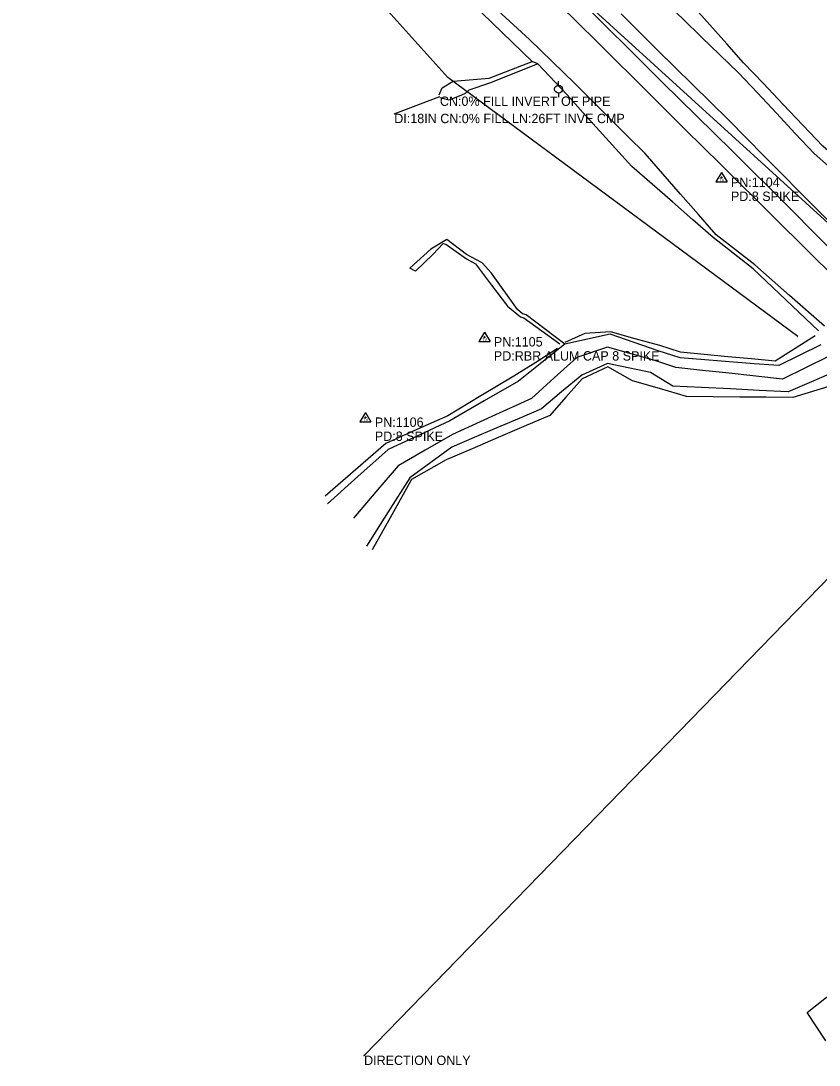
# Model space of a CAD drawing. Extents: x 1660112 to 1662239, y 668919 to 671377.
# Drawn here: x 1660814 to 1661240, y 669846 to 670403 of the extents above; entities that cross this region are included whole.
import ezdxf

# ---------------------------------------------------------------- set-up
doc = ezdxf.new("R2010")
doc.units = 0
for name, color, linetype in [('S_BASELINE', 7, 'Continuous'), ('S_DITCHLINE', 7, 'Continuous'), ('S_DRG_PT_SYM', 7, 'Continuous'), ('S_DRIVEWAY', 7, 'Continuous'), ('S_EDGE_PAVEMENT', 7, 'Continuous'), ('S_PAVEMENT_CROWN', 7, 'Continuous'), ('S_SANITARY_SEWER', 7, 'Continuous'), ('S_SANITARY_SEWER_ANNOT', 7, 'Continuous'), ('S_SECONDARY_CTL', 7, 'Continuous'), ('S_SECONDARY_CTL_ANNOT', 7, 'Continuous'), ('S_SIDE_DRAIN', 7, 'Continuous'), ('S_SIDE_DRAIN_ANNOT', 7, 'Continuous'), ('S_STREAM', 7, 'Continuous'), ('S_UTILITY_POLE', 7, 'Continuous'), ('S_UTL_PT_SYM', 7, 'Continuous'), ('S_WATER_UTILITIES', 7, 'Continuous')]:
    doc.layers.add(name, color=color, linetype=linetype)

msp = doc.modelspace()

# ---------------------------------------------------------------- linework, layer by layer
at = {"layer": 'S_BASELINE'}
msp.add_line((1660813.76, 670687.35), (1661335.19, 670212.07), dxfattribs=at)
at = {"layer": 'S_DITCHLINE'}
for points in [[(1661292.16, 670275.66), (1661274.83, 670292.21), (1661270.79, 670300.84), (1661264.75, 670307.54), (1661250.97, 670319.7), (1661237.18, 670331.85), (1661227.07, 670342.64), (1661216.95, 670353.42), (1661206.84, 670364.21), (1661196.72, 670375), (1661186.88, 670384.5), (1661177.03, 670394.01), (1661167.19, 670403.51), (1661157.34, 670413.01), (1661144.39, 670427.16), (1661131.45, 670441.31), (1661118.5, 670455.46), (1661105.55, 670469.61)], [(1661299.45, 670280.74), (1661284.47, 670292.7), (1661279.2, 670294.55), (1661276.17, 670300.4), (1661276.07, 670306.25), (1661258.9, 670321.05), (1661241.72, 670335.84), (1661231.17, 670346.95), (1661220.61, 670358.06), (1661210.06, 670369.17), (1661199.5, 670380.28), (1661190.45, 670390.39), (1661181.41, 670400.5), (1661172.36, 670410.61), (1661163.31, 670420.71), (1661149.32, 670433.4), (1661135.33, 670446.1), (1661121.34, 670458.79), (1661107.35, 670471.48)], [(1661239.43, 670237.24), (1661221.97, 670253.79), (1661204.51, 670270.33), (1661193.84, 670278.71), (1661183.17, 670287.08), (1661172.33, 670296.55), (1661161.49, 670306.02), (1661150.65, 670315.49), (1661139.81, 670324.96), (1661131.17, 670334.51), (1661122.52, 670344.05), (1661113.88, 670353.6), (1661105.24, 670363.14), (1661089.73, 670379.71), (1661086.66, 670381), (1661070.62, 670396.48), (1661054.58, 670411.96)], [(1661242.65, 670239.7), (1661224.03, 670256.09), (1661205.42, 670272.49), (1661195.13, 670280.52), (1661184.84, 670288.55), (1661175.36, 670299.38), (1661165.88, 670310.21), (1661156.4, 670321.03), (1661146.92, 670331.86), (1661137.55, 670341.19), (1661128.17, 670350.53), (1661118.79, 670359.86), (1661109.42, 670369.2), (1661097.31, 670380.98), (1661085.2, 670392.76), (1661068.34, 670408.15)], [(1661037.01, 670363.11), (1661038.52, 670366.98), (1661044.5, 670370.41), (1661063.67, 670371.99), (1661086.7, 670380.95)], [(1661089.74, 670379.7), (1661076.81, 670374.57), (1661063.88, 670369.43), (1661052.89, 670365.68), (1661050.81, 670363.81), (1661048.98, 670362.94), (1661042.37, 670360.33), (1661037.54, 670361.63)], [(1661104.14, 670230.16), (1661093.8, 670237.99), (1661083.46, 670245.82), (1661081.52, 670246.32), (1661078.79, 670248.62), (1661064.86, 670267.98), (1661059.89, 670273.58), (1661051.63, 670278.02), (1661041.16, 670286.08), (1661032.48, 670280.84), (1661021.33, 670270.78)], [(1661024.28, 670269.05), (1661033.67, 670278.04), (1661039.06, 670283.92), (1661040.59, 670283.48), (1661051.57, 670275.75), (1661056.38, 670272.93), (1661064.89, 670261.7), (1661073.41, 670250.48), (1661080.49, 670244.77), (1661082.16, 670244.13), (1661101.34, 670230.28)], [(1661024.28, 670269.05), (1661021.33, 670270.78)]]:
    msp.add_lwpolyline(points, dxfattribs=at)
at = {"layer": 'S_DRG_PT_SYM'}
for points in [[(1661037.39, 670362.29), (1661037.39, 670362.34), (1661037.39, 670362.29), (1661037.34, 670362.29), (1661037.39, 670362.29), (1661037.39, 670362.24), (1661037.39, 670362.29), (1661037.44, 670362.29)], [(1661013.05, 670353.07), (1661013.05, 670353.12), (1661013.05, 670353.07), (1661013, 670353.07), (1661013.05, 670353.07), (1661013.05, 670353.02), (1661013.05, 670353.07), (1661013.1, 670353.07)]]:
    msp.add_lwpolyline(points, dxfattribs=at)
at = {"layer": 'S_DRIVEWAY'}
msp.add_lwpolyline([(1661243.33, 669858.48), (1661233.44, 669873.57), (1661243.64, 669881.7), (1661257.23, 669871.4)], dxfattribs=at)
at = {"layer": 'S_EDGE_PAVEMENT'}
for points in [[(1661249.53, 670264.29), (1661232.81, 670280.83), (1661216.09, 670297.37), (1661206.48, 670306.91), (1661196.87, 670316.45), (1661187.26, 670325.99), (1661177.65, 670335.53), (1661168.35, 670344.75), (1661159.06, 670353.98), (1661149.76, 670363.2), (1661140.47, 670372.43), (1661130.68, 670382.11), (1661120.89, 670391.8), (1661111.1, 670401.49), (1661101.31, 670411.17)], [(1661262.8, 670277.66), (1661246.17, 670294.45), (1661229.53, 670311.23), (1661220, 670320.86), (1661210.47, 670330.49), (1661200.95, 670340.13), (1661191.42, 670349.76), (1661181.92, 670359.12), (1661172.42, 670368.49), (1661162.93, 670377.85), (1661153.43, 670387.22), (1661143.78, 670396.82), (1661134.14, 670406.42)]]:
    msp.add_lwpolyline(points, dxfattribs=at)
at = {"layer": 'S_PAVEMENT_CROWN'}
msp.add_lwpolyline([(1661256.17, 670270.41), (1661239.48, 670287.26), (1661222.79, 670304.1), (1661213.05, 670313.75), (1661203.32, 670323.4), (1661193.59, 670333.05), (1661183.85, 670342.7), (1661174.57, 670351.81), (1661165.29, 670360.92), (1661156.01, 670370.03), (1661146.73, 670379.14), (1661137.08, 670388.79), (1661127.43, 670398.43), (1661117.78, 670408.07)], dxfattribs=at)
at = {"layer": 'S_SANITARY_SEWER'}
msp.add_line((1661289.08, 670151.19), (1660996.93, 669850.58), dxfattribs=at)
at = {"layer": 'S_SECONDARY_CTL'}
for p, q in [((1661187.72, 670321.67), (1661184.71, 670316.72)), ((1661187.72, 670321.67), (1661190.67, 670316.72)), ((1661184.71, 670316.72), (1661190.67, 670316.72)), ((1661061.19, 670236.52), (1661058.18, 670231.56)), ((1661061.19, 670236.52), (1661064.14, 670231.56)), ((1661058.18, 670231.56), (1661064.14, 670231.56)), ((1660997.66, 670193.65), (1660994.65, 670188.69)), ((1660994.65, 670188.69), (1661000.61, 670188.69)), ((1660997.66, 670193.65), (1661000.61, 670188.69))]:
    msp.add_line(p, q, dxfattribs=at)
for centre, radius in [((1661187.72, 670319.06), 0.311), ((1661187.72, 670319.06), 0.183), ((1661187.72, 670319.06), 0.103), ((1661061.19, 670233.91), 0.311), ((1661061.19, 670233.91), 0.183), ((1661061.19, 670233.91), 0.103), ((1660997.66, 670191.04), 0.311), ((1660997.66, 670191.04), 0.183), ((1660997.66, 670191.04), 0.103)]:
    msp.add_circle(centre, radius, dxfattribs=at)
at = {"layer": 'S_SIDE_DRAIN'}
msp.add_line((1661013.05, 670353.07), (1661037.39, 670362.29), dxfattribs=at)
at = {"layer": 'S_STREAM'}
for points in [[(1661240.7, 670229.82), (1661218.36, 670218.7), (1661205.19, 670219.73), (1661192.01, 670220.76), (1661178.84, 670221.78), (1661165.66, 670222.81), (1661153.9, 670226.65), (1661141.09, 670231.09), (1661128.28, 670235.52), (1661104.13, 670230.16), (1661091.73, 670220.31), (1661079.33, 670210.47), (1661061.05, 670199.86), (1661042.76, 670189.25), (1661026.29, 670181.65), (1661009.82, 670174.04), (1660993.64, 670159.54), (1660977.45, 670145.03)], [(1661237.64, 670234.64), (1661226.98, 670227.9), (1661216.31, 670221.16), (1661203.67, 670222.32), (1661191.03, 670223.48), (1661178.4, 670224.64), (1661165.76, 670225.81), (1661154.74, 670229.38), (1661141.63, 670233.02), (1661128.51, 670236.67), (1661114.77, 670235.78), (1661104.13, 670231.11)], [(1661100.22, 670227.77), (1661088.57, 670220.41), (1661076.93, 670213.05), (1661059.25, 670202.53), (1661041.58, 670192), (1661025.06, 670184.59), (1661008.55, 670177.19), (1660992.32, 670163.1), (1660976.09, 670149)], [(1661244.82, 670223.57), (1661232.52, 670217.57), (1661220.23, 670211.57), (1661206.02, 670213.11), (1661191.8, 670214.64), (1661177.59, 670216.17), (1661163.37, 670217.71), (1661152.07, 670221.36), (1661139.48, 670224.92), (1661126.88, 670228.48), (1661110.47, 670223.04), (1661098.36, 670212.14), (1661086.24, 670201.24), (1661065.14, 670191.58), (1661044.04, 670181.92), (1661029.55, 670173.61), (1661015.06, 670165.29), (1661003.14, 670151.31), (1660991.22, 670137.34)], [(1661250.84, 670216.6), (1661237.04, 670210.68), (1661223.24, 670204.75), (1661207.85, 670205.5), (1661192.45, 670206.25), (1661177.06, 670207), (1661161.67, 670207.75), (1661149.8, 670215.11), (1661126.76, 670219.9), (1661113.07, 670213.68), (1661102.32, 670204.64), (1661091.57, 670195.6), (1661079.63, 670190.52), (1661067.69, 670185.43), (1661055.75, 670180.35), (1661043.81, 670175.26), (1661032.6, 670167.06), (1661021.38, 670158.86), (1661009.82, 670140.66), (1660998.25, 670122.45)], [(1661254.7, 670214.48), (1661247.25, 670208.21), (1661225.75, 670201.67), (1661211.58, 670201.81), (1661197.41, 670201.96), (1661183.24, 670202.1), (1661169.07, 670202.24), (1661154.61, 670206.46), (1661140.15, 670210.67), (1661126.98, 670218.08), (1661113.36, 670211.62), (1661104.67, 670201.88), (1661095.98, 670192.14), (1661082.19, 670186.21), (1661068.4, 670180.28), (1661054.61, 670174.34), (1661040.82, 670168.41), (1661022.25, 670157.95), (1661011.73, 670139.15), (1661001.22, 670120.35)]]:
    msp.add_lwpolyline(points, dxfattribs=at)
at = {"layer": 'S_UTILITY_POLE'}
for p, q in [((1661100.73, 670368.27), (1661100.73, 670370.4)), ((1661100.73, 670364.05), (1661100.73, 670361.99))]:
    msp.add_line(p, q, dxfattribs=at)
msp.add_circle((1661100.75, 670366.19), 2.11, dxfattribs=at)
at = {"layer": 'S_UTL_PT_SYM'}
for points in [[(1661041.63, 670372.43), (1661041.63, 670372.48), (1661041.63, 670372.43), (1661041.58, 670372.43), (1661041.63, 670372.43), (1661041.63, 670372.38), (1661041.63, 670372.43), (1661041.68, 670372.43)], [(1661228.37, 670234.25), (1661228.37, 670234.3), (1661228.37, 670234.25), (1661228.32, 670234.25), (1661228.37, 670234.25), (1661228.37, 670234.2), (1661228.37, 670234.25), (1661228.42, 670234.25)], [(1660996.93, 669850.58), (1660996.93, 669850.63), (1660996.93, 669850.58), (1660996.88, 669850.58), (1660996.93, 669850.58), (1660996.93, 669850.53), (1660996.93, 669850.58), (1660996.98, 669850.58)]]:
    msp.add_lwpolyline(points, dxfattribs=at)
at = {"layer": 'S_WATER_UTILITIES'}
for p, q in [((1661041.63, 670372.43), (1660939.86, 670485.61)), ((1661228.37, 670234.25), (1661041.63, 670372.43))]:
    msp.add_line(p, q, dxfattribs=at)

# ---------------------------------------------------------------- texts
at = {"layer": 'S_SANITARY_SEWER_ANNOT'}
msp.add_text('DIRECTION ONLY', height=5, dxfattribs=at).set_placement((1660996.93, 669845.58))
at = {"layer": 'S_SECONDARY_CTL'}
for p in [(1661186.52, 670317.05), (1661059.99, 670231.9), (1660996.46, 670189.03)]:
    msp.add_text('TV', height=1.5, rotation=360, dxfattribs=at).set_placement(p)
at = {"layer": 'S_SECONDARY_CTL_ANNOT'}
for s, p in [('PN:1104', (1661192.72, 670314.06)), ('PD:8 SPIKE', (1661192.72, 670306.56)), ('PN:1105', (1661066.19, 670228.91)), ('PD:RBR ALUM CAP 8 SPIKE', (1661066.19, 670221.41)), ('PN:1106', (1661002.66, 670186.04)), ('PD:8 SPIKE', (1661002.66, 670178.54))]:
    msp.add_text(s, height=5, dxfattribs=at).set_placement(p)
at = {"layer": 'S_SIDE_DRAIN_ANNOT'}
for s, p in [('CN:0% FILL INVERT OF PIPE', (1661037.39, 670357.29)), ('DI:18IN CN:0% FILL LN:26FT INVE CMP', (1661013.05, 670348.07))]:
    msp.add_text(s, height=5, dxfattribs=at).set_placement(p)

doc.saveas('drawing.dxf')
